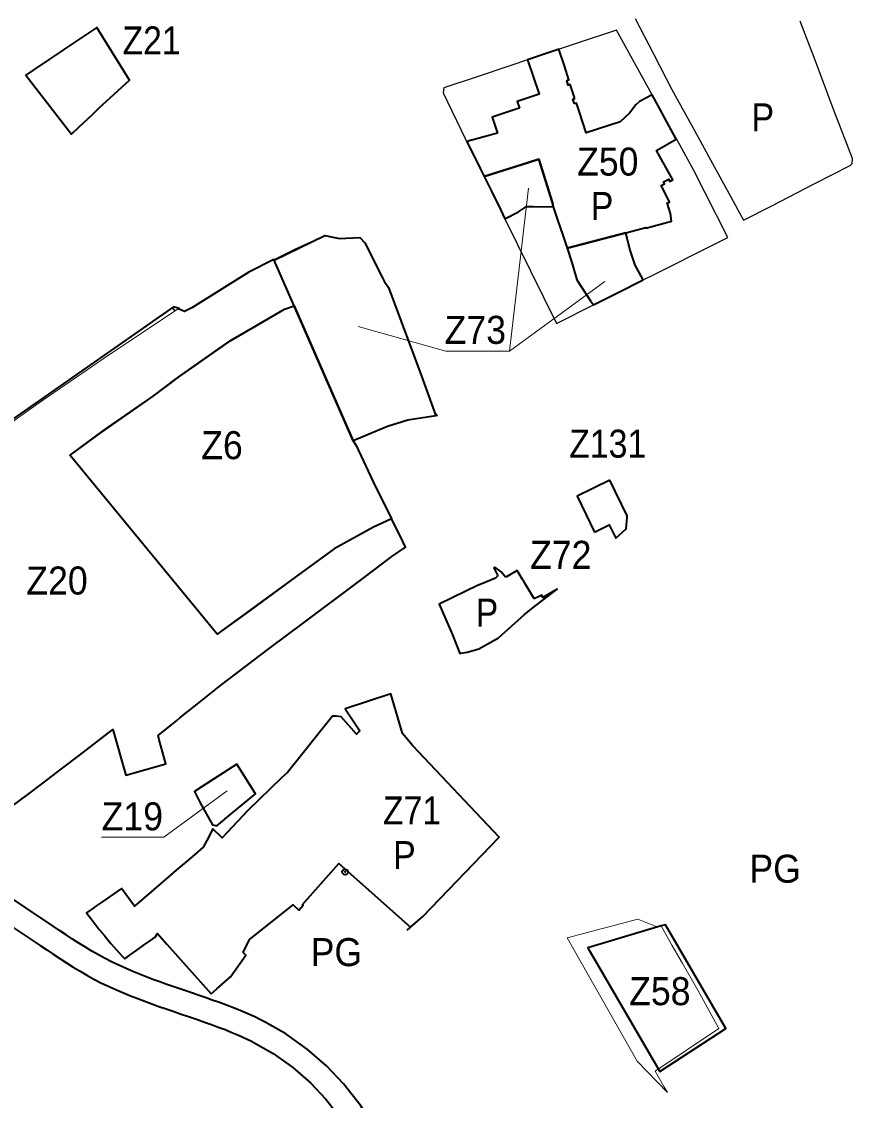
# Model space of a CAD drawing. Extents: x -650276 to -642489, y -1074311 to -1066658.
# Drawn here: x -648043 to -647332, y -1071620 to -1070697 of the extents above; entities that cross this region are included whole.
import ezdxf

# ---------------------------------------------------------------- set-up
doc = ezdxf.new("R2010")
doc.units = 0
doc.header["$LTSCALE"] = 9.6
doc.header["$PDMODE"] = 32
doc.header["$PDSIZE"] = 4.8
for name, color, linetype, lineweight in [('42', 7, 'Continuous', 25), ('44', 7, 'Continuous', 40), ('45', 7, 'Continuous', 40), ('46', 7, 'Continuous', 13), ('60', 7, 'Continuous', 35), ('63', 7, 'Continuous', 13)]:
    doc.layers.add(name, color=color, linetype=linetype, lineweight=lineweight)

msp = doc.modelspace()

# ---------------------------------------------------------------- linework, layer by layer
at = {"layer": '42'}
for points in [[(-647518.19, -1070693.93), (-647502.59, -1070724.13), (-647486.84, -1070754.54), (-647464.3, -1070795.6), (-647450.23, -1070821.25), (-647448.84, -1070823.79), (-647437.79, -1070844.12), (-647425.58, -1070866.7), (-647401.15, -1070854.25), (-647365.48, -1070835.85), (-647334.27, -1070819.86), (-647332.51, -1070817.97), (-647332.25, -1070813.72), (-647345.18, -1070779.89), (-647346.96, -1070775.41), (-647365.94, -1070725.08), (-647367.67, -1070720.73), (-647377.04, -1070696.22)], [(-647717.363, -1071306.29), (-647727.368, -1071272.362), (-647766.35, -1071285.11), (-647753.89, -1071303.94), (-647756.67, -1071306.77), (-647769.85, -1071291.91), (-647774.14, -1071291.34), (-647777.4, -1071291.32), (-647815.95, -1071339.71), (-647820.93, -1071344.25), (-647849.86, -1071372.18), (-647867.45, -1071390.95), (-647871.68, -1071395.59), (-647879.76, -1071387.96), (-647885.05, -1071397.88), (-647888.11, -1071403.61), (-647895.29, -1071409.81), (-647904.3, -1071417.58), (-647911.04, -1071423.39), (-647913.31, -1071425.35), (-647921.96, -1071432.81), (-647946.78, -1071454.23), (-647957.906, -1071439.06), (-647974.66, -1071450.62), (-647977.28, -1071452.43), (-647979.88, -1071454.22), (-647982.46, -1071456), (-647985.06, -1071457.79), (-647987.8, -1071459.68), (-647984, -1071465), (-647977.13, -1071474.05), (-647972.76, -1071479)], [(-647710.546, -1071472.023), (-647700.078, -1071462.96), (-647634.524, -1071394.901), (-647708.429, -1071316.821), (-647717.363, -1071306.29)], [(-647803.1, -1071452.66), (-647771.82, -1071417.42), (-647710.546, -1071472.023)], [(-647848.4, -1071482.78), (-647810.97, -1071452.92), (-647806.15, -1071457.48)], [(-647806.15, -1071457.48), (-647802.53, -1071453.19), (-647803.1, -1071452.66)], [(-647972.76, -1071479), (-647967.13, -1071486.01), (-647957.07, -1071497.13), (-647955.14, -1071499.23), (-647950.56, -1071495.85), (-647944.81, -1071491.78), (-647939.31, -1071487.88), (-647933.88, -1071484.04), (-647931.17, -1071482.12), (-647929.26, -1071480.77), (-647927.2, -1071477.54), (-647919.22, -1071486.5), (-647881.16, -1071529.25)], [(-647881.16, -1071529.25), (-647876.27, -1071524.96), (-647864.69, -1071514.65), (-647851.45, -1071495.96), (-647853.77, -1071493.78), (-647848.4, -1071482.78)]]:
    msp.add_lwpolyline(points, dxfattribs=at)
msp.add_lwpolyline([(-647534.33, -1070703.84), (-647567.08, -1070714.8), (-647583.22, -1070720.2), (-647651.82, -1070743.17), (-647682.08, -1070753.29), (-647682.67, -1070757.67), (-647663.71, -1070796.77), (-647585.55, -1070954.94), (-647553.94, -1070939.11), (-647532.58, -1070928.392), (-647511.37, -1070917.79), (-647501.26, -1070912.72), (-647450.8, -1070887.42), (-647438.82, -1070881.43), (-647467.89, -1070824.15), (-647480.13, -1070802.09), (-647503.76, -1070759.31)], close=True, dxfattribs=at)
at = {"layer": '44'}
for points in [[(-647834.953, -1071553.406), (-647837.929, -1071551.872), (-647843.891, -1071549), (-647849.898, -1071546.282), (-647855.937, -1071543.707), (-647861.998, -1071541.254), (-647868.073, -1071538.911), (-647874.155, -1071536.658), (-647880.233, -1071534.48), (-647886.305, -1071532.36), (-647892.363, -1071530.282), (-647901.28, -1071527.249), (-647907.294, -1071525.204), (-647913.282, -1071523.152), (-647919.238, -1071521.081), (-647925.157, -1071518.976), (-647931.035, -1071516.824), (-647936.866, -1071514.613), (-647942.644, -1071512.329), (-647948.363, -1071509.96), (-647954.016, -1071507.496), (-647959.792, -1071504.833), (-647966.547, -1071501.883), (-647972.035, -1071499.009), (-647977.67, -1071495.885), (-647983.266, -1071492.628), (-647988.829, -1071489.259), (-647994.366, -1071485.79), (-647999.887, -1071482.241), (-648005.399, -1071478.627), (-648010.917, -1071474.963), (-648016.446, -1071471.268), (-648063.593, -1071439.723)], [(-648074.86, -1071456.248), (-648027.562, -1071487.894), (-648022.005, -1071491.607), (-648016.415, -1071495.321), (-648010.777, -1071499.017), (-648005.082, -1071502.678), (-647999.319, -1071506.287), (-647993.478, -1071509.826), (-647987.55, -1071513.275), (-647981.525, -1071516.615), (-647975.201, -1071519.929), (-647967.982, -1071523.081), (-647962.2, -1071525.746), (-647956.187, -1071528.368), (-647950.146, -1071530.869), (-647944.088, -1071533.263), (-647938.019, -1071535.566), (-647931.945, -1071537.788), (-647925.874, -1071539.949), (-647919.808, -1071542.058), (-647913.756, -1071544.132), (-647907.72, -1071546.185), (-647898.827, -1071549.208), (-647892.847, -1071551.26), (-647886.903, -1071553.336), (-647881.001, -1071555.45), (-647875.147, -1071557.619), (-647869.348, -1071559.856), (-647863.611, -1071562.177), (-647857.944, -1071564.594), (-647847.103, -1071569.497)], [(-647725.629, -1071678.373), (-647735.352, -1071657.117), (-647741.34, -1071644.028), (-647753.065, -1071625.201), (-647767.784, -1071606.225), (-647782.408, -1071590.847), (-647798.911, -1071576.526), (-647817.375, -1071563.458), (-647834.953, -1071553.406)], [(-647847.103, -1071569.497), (-647828.141, -1071580.34), (-647811.272, -1071592.28), (-647796.24, -1071605.324), (-647782.97, -1071619.278)], [(-647782.97, -1071619.278), (-647769.498, -1071636.647), (-647758.994, -1071653.513), (-647743.48, -1071687.426), (-647611.514, -1071974.086)]]:
    msp.add_lwpolyline(points, dxfattribs=at)
at = {"layer": '45'}
for p, q in [((-647914.73, -1070941.682), (-647912.347, -1070944.065)), ((-647914.73, -1070941.682), (-647912.347, -1070944.065)), ((-647713.442, -1071474.53), (-647700.078, -1071462.96)), ((-647713.442, -1071474.53), (-647700.078, -1071462.96))]:
    msp.add_line(p, q, dxfattribs=at)
for points in [[(-648032.601, -1070737.472), (-648039.82, -1070742.33), (-648000.85, -1070792.88), (-647994.63, -1070787.05), (-647982.89, -1070776.05), (-647976.97, -1070770.51), (-647964.21, -1070758.77), (-647951.11, -1070746.78), (-647979.17, -1070701.65), (-648008.28, -1070720.96), (-648009.29, -1070721.79), (-648019.49, -1070728.65)], [(-647827.363, -1070900.725), (-647783.95, -1070879.58), (-647771.47, -1070882.27), (-647753.81, -1070881.3), (-647749.75, -1070886.1), (-647734.48, -1070915.94), (-647732.97, -1070918.87), (-647729.27, -1070924.35), (-647701.45, -1070999.4), (-647688.9, -1071034.18), (-647712.74, -1071037.99), (-647730.17, -1071043.21), (-647759.52, -1071055.67)], [(-647827.363, -1070900.725), (-647783.95, -1070879.58), (-647771.47, -1070882.27), (-647753.81, -1070881.3), (-647749.75, -1070886.1), (-647734.48, -1070915.94), (-647732.97, -1070918.87), (-647729.27, -1070924.35), (-647701.45, -1070999.4), (-647688.9, -1071034.18), (-647712.74, -1071037.99), (-647730.17, -1071043.21), (-647759.52, -1071055.67)], [(-648001.766, -1071068.02), (-648001.922, -1071067.83), (-647973.304, -1071046.814), (-647930.96, -1071017.383), (-647912.11, -1071003.11), (-647906.9, -1070999.39), (-647875.248, -1070977.173), (-647864.03, -1070969.3), (-647843.928, -1070957.692), (-647818.33, -1070942.91), (-647810.243, -1070939.825), (-647759.52, -1071055.67), (-647757.19, -1071059.66), (-647742.64, -1071090.72), (-647726.74, -1071122.48), (-647742.35, -1071129.43), (-647775.982, -1071148.001), (-647775.982, -1071148.001), (-647875.939, -1071221.104)], [(-647974.66, -1071450.62), (-647977.28, -1071452.43), (-647979.88, -1071454.22), (-647982.46, -1071456), (-647985.06, -1071457.79), (-647987.8, -1071459.68), (-647984, -1071465), (-647977.13, -1071474.05), (-647972.76, -1071479), (-647967.13, -1071486.01), (-647957.07, -1071497.13), (-647955.14, -1071499.23), (-647950.56, -1071495.85), (-647944.81, -1071491.78), (-647939.31, -1071487.88), (-647933.88, -1071484.04), (-647931.17, -1071482.12), (-647929.26, -1071480.77), (-647927.2, -1071477.54), (-647919.22, -1071486.5), (-647881.16, -1071529.25), (-647876.27, -1071524.96), (-647864.69, -1071514.65), (-647851.45, -1071495.96), (-647853.77, -1071493.78), (-647848.4, -1071482.78), (-647810.97, -1071452.92), (-647806.15, -1071457.48), (-647802.53, -1071453.19), (-647803.1, -1071452.66), (-647771.82, -1071417.42), (-647710.546, -1071472.023), (-647700.078, -1071462.96), (-647634.524, -1071394.901), (-647708.429, -1071316.821), (-647717.363, -1071306.29), (-647727.368, -1071272.362), (-647766.35, -1071285.11), (-647753.89, -1071303.94), (-647756.67, -1071306.77), (-647769.85, -1071291.91), (-647774.14, -1071291.34), (-647777.4, -1071291.32), (-647815.95, -1071339.71), (-647820.93, -1071344.25), (-647849.86, -1071372.18), (-647867.45, -1071390.95), (-647871.68, -1071395.59), (-647879.76, -1071387.96), (-647885.05, -1071397.88), (-647888.11, -1071403.61), (-647895.29, -1071409.81), (-647904.3, -1071417.58), (-647911.04, -1071423.39), (-647913.31, -1071425.35), (-647921.96, -1071432.81), (-647946.78, -1071454.23), (-647957.906, -1071439.06)], [(-647974.66, -1071450.62), (-647977.28, -1071452.43), (-647979.88, -1071454.22), (-647982.46, -1071456), (-647985.06, -1071457.79), (-647987.8, -1071459.68), (-647984, -1071465), (-647977.13, -1071474.05), (-647972.76, -1071479), (-647967.13, -1071486.01), (-647957.07, -1071497.13), (-647955.14, -1071499.23), (-647950.56, -1071495.85), (-647944.81, -1071491.78), (-647939.31, -1071487.88), (-647933.88, -1071484.04), (-647931.17, -1071482.12), (-647929.26, -1071480.77), (-647927.2, -1071477.54), (-647919.22, -1071486.5), (-647881.16, -1071529.25), (-647876.27, -1071524.96), (-647864.69, -1071514.65), (-647851.45, -1071495.96), (-647853.77, -1071493.78), (-647848.4, -1071482.78), (-647810.97, -1071452.92), (-647806.15, -1071457.48), (-647802.53, -1071453.19), (-647803.1, -1071452.66), (-647771.82, -1071417.42), (-647710.546, -1071472.023), (-647700.078, -1071462.96), (-647634.524, -1071394.901), (-647708.429, -1071316.821), (-647717.363, -1071306.29), (-647727.368, -1071272.362), (-647766.35, -1071285.11), (-647753.89, -1071303.94), (-647756.67, -1071306.77), (-647769.85, -1071291.91), (-647774.14, -1071291.34), (-647777.4, -1071291.32), (-647815.95, -1071339.71), (-647820.93, -1071344.25), (-647849.86, -1071372.18), (-647867.45, -1071390.95), (-647871.68, -1071395.59), (-647879.76, -1071387.96), (-647885.05, -1071397.88), (-647888.11, -1071403.61), (-647895.29, -1071409.81), (-647904.3, -1071417.58), (-647911.04, -1071423.39), (-647913.31, -1071425.35), (-647921.96, -1071432.81), (-647946.78, -1071454.23), (-647957.906, -1071439.06)], [(-647879.09, -1071345.3), (-647895.37, -1071355.96), (-647890.7, -1071365.52), (-647880.14, -1071384.32), (-647876.34, -1071385.2), (-647862.25, -1071373.55), (-647859.44, -1071371.23), (-647843.23, -1071357.82), (-647859.31, -1071332.34)], [(-647879.09, -1071345.3), (-647895.37, -1071355.96), (-647890.7, -1071365.52), (-647880.14, -1071384.32), (-647876.34, -1071385.2), (-647862.25, -1071373.55), (-647859.44, -1071371.23), (-647843.23, -1071357.82), (-647859.31, -1071332.34)], [(-647497.04, -1071595.66), (-647440.67, -1071558.93), (-647492.3, -1071470), (-647495.85, -1071471.06), (-647558.654, -1071489.738)], [(-647497.04, -1071595.66), (-647440.67, -1071558.93), (-647492.3, -1071470), (-647495.85, -1071471.06), (-647558.654, -1071489.738)]]:
    msp.add_lwpolyline(points, close=True, dxfattribs=at)
for points in [[(-647569.92, -1070762.24), (-647573.88, -1070750.25), (-647575.58, -1070750.83), (-647576.81, -1070746.86), (-647575.09, -1070746.33), (-647578.79, -1070734.33), (-647583.38, -1070720.9), (-647583.22, -1070720.2), (-647593.6, -1070723.68), (-647610.33, -1070729.28), (-647600.53, -1070758.65), (-647619.2, -1070764.85), (-647617.36, -1070770.69)], [(-647636.12, -1070792.13), (-647654.89, -1070797.23), (-647662.26, -1070799.23), (-647650.908, -1070822.34), (-647647.405, -1070829.08), (-647609.58, -1070817.06), (-647600.8, -1070814.27), (-647588.89, -1070851.67), (-647588.4, -1070855.25), (-647584.6, -1070866.3), (-647580.22, -1070879.3), (-647578.703, -1070883.851), (-647578.703, -1070883.851), (-647576.469, -1070890.564), (-647526.13, -1070877.41), (-647509.1, -1070872.96), (-647508.96, -1070873.41), (-647487.16, -1070867.32), (-647487.91, -1070860.91), (-647490.92, -1070851.82), (-647488.8, -1070851.12), (-647494.1, -1070840.58), (-647495.93, -1070836.86), (-647493.16, -1070835.5), (-647494.03, -1070833.64), (-647489.55, -1070831.53), (-647488.75, -1070833.37), (-647485.9, -1070832), (-647500.07, -1070806.87), (-647500.07, -1070806.87), (-647483.16, -1070797.07), (-647492.81, -1070779.18), (-647492.81, -1070779.18), (-647497.227, -1070771.165), (-647503.76, -1070759.31), (-647514.49, -1070764.93), (-647517.61, -1070767.89), (-647523.07, -1070774.86), (-647531.05, -1070782.23), (-647560.06, -1070791.72), (-647566.26, -1070773.148)], [(-647570.27, -1070766.86), (-647571.63, -1070762.82), (-647569.92, -1070762.24)], [(-647566.26, -1070773.148), (-647568.55, -1070766.29), (-647570.27, -1070766.86)], [(-647617.36, -1070770.69), (-647619.12, -1070771.28), (-647640.66, -1070778.47), (-647636.12, -1070792.13)], [(-647588.4, -1070855.25), (-647588.89, -1070851.67), (-647600.8, -1070814.27), (-647609.58, -1070817.06), (-647647.405, -1070829.08)], [(-647588.4, -1070855.25), (-647588.89, -1070851.67), (-647600.8, -1070814.27), (-647609.58, -1070817.06), (-647647.405, -1070829.08)], [(-647647.405, -1070829.08), (-647635.11, -1070853.786), (-647629.92, -1070865.35), (-647618.01, -1070859.42), (-647611.3, -1070854.9), (-647605.64, -1070854.99), (-647588.4, -1070855.25)], [(-647647.405, -1070829.08), (-647635.11, -1070853.786), (-647629.92, -1070865.35), (-647618.01, -1070859.42), (-647611.3, -1070854.9), (-647605.64, -1070854.99), (-647588.4, -1070855.25)], [(-647511.37, -1070917.79), (-647516.66, -1070907.8), (-647518.12, -1070905.05), (-647522.74, -1070891.48), (-647526.13, -1070877.41), (-647576.469, -1070890.564)], [(-647576.469, -1070890.564), (-647576.43, -1070890.68), (-647572.32, -1070902.72), (-647568.2, -1070917.54), (-647556.52, -1070935.59), (-647553.94, -1070939.11)], [(-648060.01, -1071374.69), (-648038.18, -1071358.51), (-648025.39, -1071348.76), (-648009.31, -1071336.48), (-647994.31, -1071325.03), (-647965.26, -1071302.86), (-647954.38, -1071342), (-647919.88, -1071332.23), (-647925.6, -1071311.69), (-647926.69, -1071307.81), (-647910.73, -1071295.08), (-647907.92, -1071292.84), (-647888.77, -1071277.56), (-647873.25, -1071265.17), (-647831.565, -1071233.455), (-647801.178, -1071210.742), (-647756.03, -1071176.76), (-647750.34, -1071172.5), (-647726.56, -1071154.68), (-647714.71, -1071146.51), (-647714.71, -1071146.51), (-647719.73, -1071136.48), (-647726.74, -1071122.48), (-647742.35, -1071129.43), (-647775.982, -1071148.001), (-647808.402, -1071171.711), (-647848.51, -1071201.045), (-647875.939, -1071221.104), (-648001.766, -1071068.02), (-648001.922, -1071067.83), (-647977.41, -1071049.74), (-647930.96, -1071017.383), (-647911.838, -1071002.919), (-647912.11, -1071003.11), (-647864.29, -1070969.503), (-647838.842, -1070954.778), (-647818.33, -1070942.91), (-647810.243, -1070939.825), (-647827.527, -1070900.351), (-647848.89, -1070911.21), (-647897.76, -1070941.62), (-647904.13, -1070944.78), (-647909.42, -1070942.63), (-647908.63, -1070942.1), (-647913.45, -1070940.79), (-648062.53, -1071044.59)], [(-647553.94, -1070939.11), (-647553.94, -1070939.11), (-647550.59, -1070937.45), (-647533.31, -1070928.79), (-647511.37, -1070917.79)], [(-647539.818, -1071089.2), (-647568.01, -1071102.98), (-647553.01, -1071133.68)], [(-647525.1, -1071121.25), (-647524.95, -1071119.68), (-647539.817, -1071089.199)], [(-647553.01, -1071133.68), (-647540.48, -1071127.55), (-647534.851, -1071139.015), (-647526.04, -1071130.94), (-647525.1, -1071121.25)], [(-647629.09, -1071172.4), (-647632.93, -1071167.71), (-647638.46, -1071163.89), (-647639.32, -1071164.22), (-647635.93, -1071171.22)], [(-647629.09, -1071172.4), (-647632.93, -1071167.71), (-647638.46, -1071163.89), (-647639.32, -1071164.22), (-647635.93, -1071171.22)], [(-647635.93, -1071171.22), (-647637.87, -1071173.29), (-647646.09, -1071176.68), (-647653.85, -1071179.87), (-647662.634, -1071183.968)], [(-647635.93, -1071171.22), (-647637.87, -1071173.29), (-647646.09, -1071176.68), (-647653.85, -1071179.87), (-647662.634, -1071183.968)], [(-647612.695, -1071177.542), (-647613.91, -1071175.57), (-647614.732, -1071174.222), (-647618.446, -1071168.166), (-647618.469, -1071168.129), (-647618.77, -1071167.64), (-647619.264, -1071166.832), (-647619.34, -1071166.709), (-647628.39, -1071172.05), (-647629.09, -1071172.4)], [(-647612.695, -1071177.542), (-647613.91, -1071175.57), (-647614.732, -1071174.222), (-647618.446, -1071168.166), (-647618.469, -1071168.129), (-647618.77, -1071167.64), (-647619.264, -1071166.832), (-647619.34, -1071166.709), (-647628.39, -1071172.05), (-647629.09, -1071172.4)], [(-647674.6, -1071221.71), (-647668.226, -1071237.571), (-647667.77, -1071237.5), (-647661.99, -1071236.62), (-647658.78, -1071235.63), (-647651.93, -1071233.57), (-647635.17, -1071224.18), (-647613.09, -1071204.33), (-647607.02, -1071199.34), (-647584.92, -1071182.54), (-647597.164, -1071189.857), (-647598.215, -1071187.608), (-647604.576, -1071190.781)], [(-647674.6, -1071221.71), (-647668.226, -1071237.571), (-647667.77, -1071237.5), (-647661.99, -1071236.62), (-647658.78, -1071235.63), (-647651.93, -1071233.57), (-647635.17, -1071224.18), (-647613.09, -1071204.33), (-647607.02, -1071199.34), (-647584.92, -1071182.54), (-647597.164, -1071189.857), (-647598.215, -1071187.608), (-647604.576, -1071190.781)], [(-647604.576, -1071190.781), (-647604.888, -1071190.272), (-647612.695, -1071177.542)], [(-647604.576, -1071190.781), (-647604.888, -1071190.272), (-647612.695, -1071177.542)], [(-647662.634, -1071183.968), (-647686.01, -1071195.35), (-647686.01, -1071195.35)], [(-647662.634, -1071183.968), (-647686.01, -1071195.35), (-647686.01, -1071195.35)], [(-647686.01, -1071195.35), (-647686.01, -1071195.35), (-647674.6, -1071221.71)], [(-647686.01, -1071195.35), (-647686.01, -1071195.35), (-647674.6, -1071221.71)]]:
    msp.add_lwpolyline(points, dxfattribs=at)
msp.add_point((-647766.557, -1071424.793), dxfattribs=at)
at = {"layer": '46'}
for points in [[(-647544.337, -1070919.163), (-647625.809, -1070978.773), (-647609.46, -1070839.305), (-647625.809, -1070978.773), (-647680.348, -1070978.773), (-647755.299, -1070957.715)], [(-647544.337, -1070919.163), (-647625.809, -1070978.773), (-647609.46, -1070839.305), (-647625.809, -1070978.773), (-647680.348, -1070978.773), (-647755.299, -1070957.715)], [(-647974.97, -1071395.111), (-647921.786, -1071395.111), (-647867.57, -1071355.322)], [(-647974.97, -1071395.111), (-647921.786, -1071395.111), (-647867.57, -1071355.322)]]:
    msp.add_lwpolyline(points, dxfattribs=at)
at = {"layer": '63'}
msp.add_line((-647516.376, -1071586.89), (-647490.56, -1071613.611), dxfattribs=at)
for points in [[(-647954.38, -1071342), (-647919.88, -1071332.23), (-647926.69, -1071307.81), (-647910.73, -1071295.08), (-647907.92, -1071292.84), (-647888.77, -1071277.56), (-647873.25, -1071265.17), (-647820.78, -1071225.25), (-647756.03, -1071176.76), (-647750.34, -1071172.5), (-647720.85, -1071150.41), (-647714.71, -1071146.51), (-647719.73, -1071136.48), (-647722.51, -1071130.93), (-647726.74, -1071122.48), (-647742.64, -1071090.72), (-647757.19, -1071059.66), (-647759.52, -1071055.67), (-647730.17, -1071043.21), (-647712.74, -1071037.99), (-647688.9, -1071034.18), (-647687.41, -1071034.25), (-647690.22, -1071030.28), (-647701.45, -1070999.4), (-647724.603, -1070936.951), (-647729.27, -1070924.35), (-647732.97, -1070918.87), (-647734.48, -1070915.94), (-647741.21, -1070902.78), (-647749.75, -1070886.1), (-647753.81, -1070881.3), (-647771.47, -1070882.27), (-647783.95, -1070879.58), (-647790.016, -1070882.333), (-647809.74, -1070891.31), (-647848.89, -1070911.21), (-647897.76, -1070941.62), (-647904.13, -1070944.78), (-647909.42, -1070942.63), (-647969.116, -1070982.149), (-648029.353, -1071023.703), (-648084.716, -1071062.607)], [(-648091.92, -1071399.07), (-648074.27, -1071385.62), (-648071.17, -1071383.26), (-648064.98, -1071378.51), (-648060.01, -1071374.69), (-648038.18, -1071358.51), (-648025.39, -1071348.76), (-648009.31, -1071336.48), (-647994.31, -1071325.03), (-647965.26, -1071302.86), (-647954.38, -1071342)], [(-647490.56, -1071613.611), (-647493.6, -1071608.5), (-647501.11, -1071595.45), (-647446.68, -1071558.91), (-647464.47, -1071526.06), (-647477.86, -1071502.65), (-647486.94, -1071487.42), (-647495.85, -1071471.06), (-647498.8, -1071471.94), (-647515.87, -1071465.25), (-647576.471, -1071481.091)], [(-647576.471, -1071481.091), (-647516.376, -1071586.89), (-647516.376, -1071586.89)]]:
    msp.add_lwpolyline(points, dxfattribs=at)

# ---------------------------------------------------------------- texts
at = {"layer": '46'}
for s, width, p in [('Z21', 0.9, (-647957.11, -1070724.677)), ('Z50', 0.95, (-647567.967, -1070828.405)), ('Z50', 0.95, (-647567.967, -1070828.405)), ('Z73', 0.95, (-647681.324, -1070972.53)), ('Z73', 0.95, (-647681.324, -1070972.53)), ('Z6', 0.95, (-647889.738, -1071071.271)), ('Z131', 0.9, (-647574.644, -1071069.985)), ('Z72', 0.95, (-647608.212, -1071165.192)), ('Z72', 0.95, (-647608.212, -1071165.192)), ('Z20', 0.95, (-648039.444, -1071187.201)), ('Z19', 0.95, (-647974.958, -1071389.14)), ('Z19', 0.95, (-647974.958, -1071389.14)), ('Z71', 0.9, (-647734.152, -1071384.125)), ('Z71', 0.9, (-647734.152, -1071384.125)), ('Z58', 0.95, (-647523.363, -1071538.888)), ('Z58', 0.95, (-647523.363, -1071538.888))]:
    msp.add_text(s, height=24, dxfattribs=dict(at, width=width)).set_placement(p)
at = {"layer": '60'}
for s, width, p in [('P', 0.9, (-647418.572, -1070790.564)), ('P', 0.9, (-647418.572, -1070790.564)), ('P', 0.9, (-647556.162, -1070866.47)), ('P', 0.9, (-647556.162, -1070866.47)), ('P', 0.9, (-647654.706, -1071214.743)), ('P', 0.9, (-647654.706, -1071214.743)), ('P', 0.9, (-647725.36, -1071422.368)), ('P', 0.9, (-647725.36, -1071422.368)), ('PG', 0.95, (-647420.449, -1071434.013)), ('PG', 0.95, (-647420.449, -1071434.013)), ('PG', 0.95, (-647796.031, -1071505.454)), ('PG', 0.95, (-647796.031, -1071505.454))]:
    msp.add_text(s, height=24, dxfattribs=dict(at, width=width)).set_placement(p)

doc.saveas('drawing.dxf')
